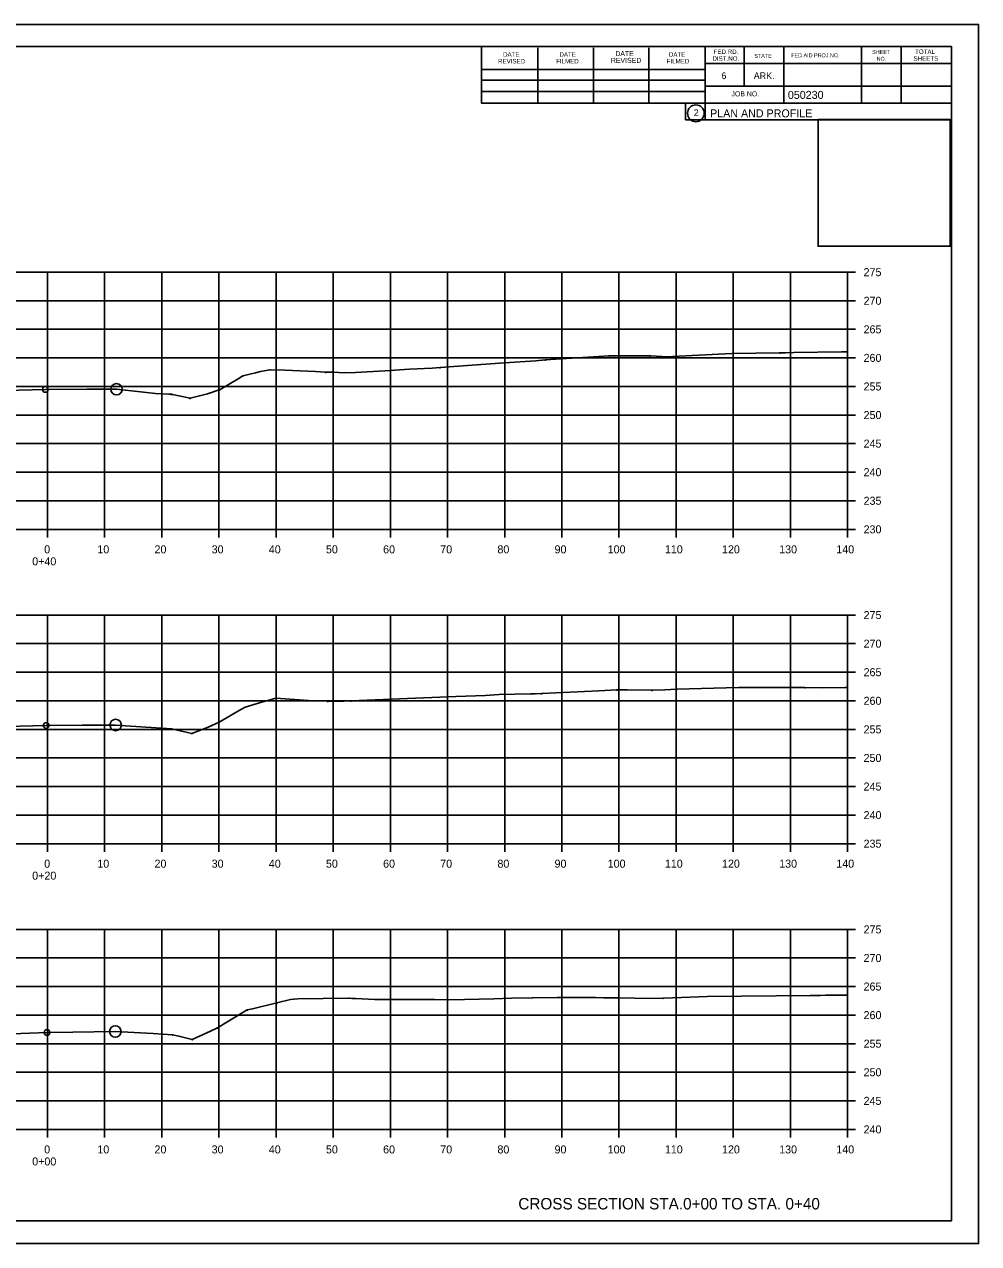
# Model space of a CAD drawing. Extents: x 1300404 to 1323571, y 234004 to 252077.
# Drawn here: x 1315713.2 to 1315880.2, y 239995.1 to 240208.4 of the extents above; entities that cross this region are included whole.
import ezdxf

# ---------------------------------------------------------------- set-up
doc = ezdxf.new("R2010")
doc.units = 0
for name, color, linetype in [('Default', 7, 'Continuous'), ('R_Axis', 7, 'Continuous'), ('R_Axis Annot', 7, 'Continuous'), ('R_Border', 7, 'Continuous'), ('R_Border Prem', 7, 'Continuous'), ('R_Draft', 7, 'Continuous'), ('R_Exist Surface', 7, 'Continuous'), ('R_Grid', 7, 'Continuous'), ('R_No Plot', 7, 'Continuous')]:
    doc.layers.add(name, color=color, linetype=linetype)

msp = doc.modelspace()

# ---------------------------------------------------------------- linework, layer by layer
at = {"layer": 'Default'}
for p, q in [((1315559.28, 240204.52), (1315875.46, 240204.52)), ((1315793.2, 240194.64), (1315793.2, 240204.52)), ((1315803.06, 240194.64), (1315803.06, 240204.32)), ((1315812.82, 240194.64), (1315812.82, 240204.32)), ((1315822.5, 240194.64), (1315822.5, 240204.32)), ((1315832.36, 240204.52), (1315832.36, 240191.72)), ((1315839.2, 240204.52), (1315839.2, 240197.58)), ((1315846.14, 240204.52), (1315846.14, 240194.64)), ((1315859.72, 240204.52), (1315859.72, 240194.64)), ((1315866.66, 240204.52), (1315866.66, 240194.64)), ((1315875.46, 239999.06), (1315875.46, 240204.52)), ((1315875.46, 240201.58), (1315832.36, 240201.58)), ((1315875.46, 240201.6), (1315875.46, 240201.6)), ((1315793.2, 240200.5), (1315832.36, 240200.5)), ((1315793.2, 240198.64), (1315832.36, 240198.64)), ((1315875.46, 240197.58), (1315832.36, 240197.58)), ((1315835.32, 240197.58), (1315875.46, 240197.58)), ((1315793.2, 240194.64), (1315793.2, 240196.7)), ((1315793.2, 240196.7), (1315832.36, 240196.7)), ((1315875.46, 240194.64), (1315793.2, 240194.64)), ((1315832.36, 240191.72), (1315875.46, 240191.72)), ((1315875.46, 239999.06), (1315559.28, 239999.06))]:
    msp.add_line(p, q, dxfattribs=at)
msp.add_circle((1315830.74, 240192.86), 1.47, dxfattribs=at)
at = {"layer": 'R_Axis'}
for p, q in [((1315857.28, 240120.06), (1315857.28, 240165.06)), ((1315858.68, 240165.06), (1315857.28, 240165.06)), ((1315858.68, 240160.06), (1315857.28, 240160.06)), ((1315858.68, 240155.06), (1315857.28, 240155.06)), ((1315858.68, 240150.06), (1315857.28, 240150.06)), ((1315858.68, 240145.06), (1315857.28, 240145.06)), ((1315858.68, 240140.06), (1315857.28, 240140.06)), ((1315858.68, 240135.06), (1315857.28, 240135.06)), ((1315858.68, 240130.06), (1315857.28, 240130.06)), ((1315858.68, 240125.06), (1315857.28, 240125.06)), ((1315577.28, 240120.06), (1315857.28, 240120.06)), ((1315717.28, 240118.66), (1315717.28, 240120.06)), ((1315727.28, 240118.66), (1315727.28, 240120.06)), ((1315737.28, 240118.66), (1315737.28, 240120.06)), ((1315747.28, 240118.66), (1315747.28, 240120.06)), ((1315757.28, 240118.66), (1315757.28, 240120.06)), ((1315767.28, 240118.66), (1315767.28, 240120.06)), ((1315777.28, 240118.66), (1315777.28, 240120.06)), ((1315787.28, 240118.66), (1315787.28, 240120.06)), ((1315797.28, 240118.66), (1315797.28, 240120.06)), ((1315807.28, 240118.66), (1315807.28, 240120.06)), ((1315817.28, 240118.66), (1315817.28, 240120.06)), ((1315827.28, 240118.66), (1315827.28, 240120.06)), ((1315837.28, 240118.66), (1315837.28, 240120.06)), ((1315847.28, 240118.66), (1315847.28, 240120.06)), ((1315857.28, 240118.66), (1315857.28, 240120.06)), ((1315858.68, 240120.06), (1315857.28, 240120.06)), ((1315857.28, 240065.06), (1315857.28, 240105.06)), ((1315858.68, 240105.06), (1315857.28, 240105.06)), ((1315858.68, 240100.06), (1315857.28, 240100.06)), ((1315858.68, 240095.06), (1315857.28, 240095.06)), ((1315858.68, 240090.06), (1315857.28, 240090.06)), ((1315858.68, 240085.06), (1315857.28, 240085.06)), ((1315858.68, 240080.06), (1315857.28, 240080.06)), ((1315858.68, 240075.06), (1315857.28, 240075.06)), ((1315858.68, 240070.06), (1315857.28, 240070.06)), ((1315577.28, 240065.06), (1315857.28, 240065.06)), ((1315717.28, 240063.66), (1315717.28, 240065.06)), ((1315727.28, 240063.66), (1315727.28, 240065.06)), ((1315737.28, 240063.66), (1315737.28, 240065.06)), ((1315747.28, 240063.66), (1315747.28, 240065.06)), ((1315757.28, 240063.66), (1315757.28, 240065.06)), ((1315767.28, 240063.66), (1315767.28, 240065.06)), ((1315777.28, 240063.66), (1315777.28, 240065.06)), ((1315787.28, 240063.66), (1315787.28, 240065.06)), ((1315797.28, 240063.66), (1315797.28, 240065.06)), ((1315807.28, 240063.66), (1315807.28, 240065.06)), ((1315817.28, 240063.66), (1315817.28, 240065.06)), ((1315827.28, 240063.66), (1315827.28, 240065.06)), ((1315837.28, 240063.66), (1315837.28, 240065.06)), ((1315847.28, 240063.66), (1315847.28, 240065.06)), ((1315857.28, 240063.66), (1315857.28, 240065.06)), ((1315858.68, 240065.06), (1315857.28, 240065.06)), ((1315857.28, 240015.06), (1315857.28, 240050.06)), ((1315858.68, 240050.06), (1315857.28, 240050.06)), ((1315858.68, 240045.06), (1315857.28, 240045.06)), ((1315858.68, 240040.06), (1315857.28, 240040.06)), ((1315858.68, 240035.06), (1315857.28, 240035.06)), ((1315858.68, 240030.06), (1315857.28, 240030.06)), ((1315858.68, 240025.06), (1315857.28, 240025.06)), ((1315858.68, 240020.06), (1315857.28, 240020.06)), ((1315577.28, 240015.06), (1315857.28, 240015.06)), ((1315717.28, 240013.66), (1315717.28, 240015.06)), ((1315727.28, 240013.66), (1315727.28, 240015.06)), ((1315737.28, 240013.66), (1315737.28, 240015.06)), ((1315747.28, 240013.66), (1315747.28, 240015.06)), ((1315757.28, 240013.66), (1315757.28, 240015.06)), ((1315767.28, 240013.66), (1315767.28, 240015.06)), ((1315777.28, 240013.66), (1315777.28, 240015.06)), ((1315787.28, 240013.66), (1315787.28, 240015.06)), ((1315797.28, 240013.66), (1315797.28, 240015.06)), ((1315807.28, 240013.66), (1315807.28, 240015.06)), ((1315817.28, 240013.66), (1315817.28, 240015.06)), ((1315827.28, 240013.66), (1315827.28, 240015.06)), ((1315837.28, 240013.66), (1315837.28, 240015.06)), ((1315847.28, 240013.66), (1315847.28, 240015.06)), ((1315857.28, 240013.66), (1315857.28, 240015.06)), ((1315858.68, 240015.06), (1315857.28, 240015.06))]:
    msp.add_line(p, q, dxfattribs=at)
at = {"layer": 'R_Draft'}
for points in [[(1315815.58, 240150.48), (1315815.63, 240150.38), (1315815.53, 240150.38)], [(1315822.72, 240150.47), (1315822.77, 240150.37), (1315822.67, 240150.37)], [(1315845.44, 240151.01), (1315845.49, 240150.91), (1315845.39, 240150.91)], [(1315756.17, 240148.05), (1315756.22, 240147.95), (1315756.12, 240147.95)], [(1315785.98, 240148.41), (1315786.03, 240148.31), (1315785.93, 240148.31)], [(1315804.38, 240149.75), (1315804.43, 240149.65), (1315804.33, 240149.65)], [(1315751.49, 240146.97), (1315751.54, 240146.87), (1315751.44, 240146.87)], [(1315765.91, 240147.61), (1315765.96, 240147.51), (1315765.86, 240147.51)], [(1315738.97, 240143.74), (1315739.02, 240143.64), (1315738.92, 240143.64)], [(1315747.5, 240144.59), (1315747.55, 240144.49), (1315747.45, 240144.49)], [(1315742.24, 240143.05), (1315742.29, 240142.95), (1315742.19, 240142.95)], [(1315849.8, 240092.41), (1315849.85, 240092.31), (1315849.75, 240092.31)], [(1315757.26, 240090.58), (1315757.31, 240090.48), (1315757.21, 240090.48)], [(1315803.75, 240091.36), (1315803.8, 240091.26), (1315803.7, 240091.26)], [(1315816.9, 240092.03), (1315816.95, 240091.93), (1315816.85, 240091.93)], [(1315823.06, 240091.95), (1315823.11, 240091.85), (1315823.01, 240091.85)], [(1315827.4, 240092.15), (1315827.45, 240092.05), (1315827.35, 240092.05)], [(1315751.88, 240089.02), (1315751.93, 240088.92), (1315751.83, 240088.92)], [(1315766.29, 240090.03), (1315766.34, 240089.93), (1315766.24, 240089.93)], [(1315770.41, 240090.08), (1315770.46, 240089.98), (1315770.36, 240089.98)], [(1315747.32, 240086.35), (1315747.37, 240086.25), (1315747.27, 240086.25)], [(1315739.06, 240085.18), (1315739.11, 240085.08), (1315739.01, 240085.08)], [(1315742.54, 240084.4), (1315742.59, 240084.3), (1315742.49, 240084.3)], [(1315757.44, 240037.26), (1315757.49, 240037.16), (1315757.39, 240037.16)], [(1315802.15, 240038.16), (1315802.2, 240038.06), (1315802.1, 240038.06)], [(1315824.98, 240038.09), (1315825.03, 240037.99), (1315824.93, 240037.99)], [(1315850.79, 240038.57), (1315850.84, 240038.47), (1315850.74, 240038.47)], [(1315752.25, 240036.01), (1315752.3, 240035.91), (1315752.2, 240035.91)], [(1315747.04, 240032.88), (1315747.09, 240032.78), (1315746.99, 240032.78)], [(1315739.15, 240031.68), (1315739.2, 240031.58), (1315739.1, 240031.58)], [(1315742.61, 240030.84), (1315742.66, 240030.74), (1315742.56, 240030.74)]]:
    msp.add_lwpolyline(points, close=True, dxfattribs=at)
at = {"layer": 'R_Exist Surface'}
for points in [[(1315709.91, 240144.38), (1315716.91, 240144.54), (1315724.17, 240144.57), (1315729.36, 240144.57), (1315736.19, 240143.84), (1315738.51, 240143.72), (1315738.97, 240143.69), (1315739.13, 240143.65), (1315742.24, 240143), (1315745.26, 240143.78), (1315747.5, 240144.54), (1315750.64, 240146.42), (1315751.49, 240146.92), (1315753.68, 240147.45), (1315754.56, 240147.7), (1315756.17, 240148), (1315758.82, 240147.91), (1315764.18, 240147.68), (1315765.91, 240147.56), (1315767.21, 240147.56), (1315769.3, 240147.47), (1315771.2, 240147.49), (1315776.29, 240147.79), (1315780.61, 240148.06), (1315784.59, 240148.25), (1315785.98, 240148.36), (1315797.21, 240149.18), (1315802.73, 240149.56), (1315804.38, 240149.7), (1315805.31, 240149.78), (1315815.58, 240150.43), (1315816.86, 240150.44), (1315822.72, 240150.42), (1315825.88, 240150.24), (1315826.25, 240150.26), (1315826.62, 240150.28), (1315837.04, 240150.85), (1315845.44, 240150.96), (1315846.4, 240150.96), (1315847.85, 240150.98), (1315856.23, 240151.11), (1315857.28, 240151.11)], [(1315707.7, 240085.49), (1315717.07, 240085.72), (1315723.38, 240085.79), (1315729.21, 240085.82), (1315737.16, 240085.25), (1315739.06, 240085.13), (1315739.77, 240084.97), (1315742.54, 240084.35), (1315745.38, 240085.42), (1315747.32, 240086.3), (1315751.12, 240088.51), (1315751.88, 240088.97), (1315754.36, 240089.7), (1315757.26, 240090.53), (1315762.96, 240090.13), (1315766.29, 240089.98), (1315768.15, 240089.94), (1315769.16, 240089.97), (1315770.41, 240090.03), (1315788.72, 240090.84), (1315793.94, 240091), (1315796.32, 240091.15), (1315801.78, 240091.25), (1315802.64, 240091.28), (1315803.75, 240091.31), (1315813.73, 240091.79), (1315816.9, 240091.98), (1315818.74, 240091.96), (1315823.06, 240091.9), (1315825.3, 240091.99), (1315827.4, 240092.1), (1315838.17, 240092.37), (1315849.8, 240092.36), (1315852.9, 240092.33), (1315856.86, 240092.36), (1315857.28, 240092.37)], [(1315706.45, 240031.62), (1315717.2, 240032.04), (1315721.73, 240032.08), (1315729.15, 240032.19), (1315735.78, 240031.86), (1315739.15, 240031.63), (1315740.27, 240031.4), (1315742.61, 240030.79), (1315745.8, 240032.27), (1315747.04, 240032.83), (1315751.36, 240035.44), (1315752.25, 240035.96), (1315753.15, 240036.19), (1315757.44, 240037.21), (1315759.83, 240037.81), (1315761.1, 240037.93), (1315769.93, 240038.04), (1315770.15, 240038.03), (1315770.56, 240037.99), (1315770.73, 240037.97), (1315770.87, 240037.96), (1315771.06, 240037.95), (1315771.26, 240037.94), (1315774.55, 240037.8), (1315775.79, 240037.78), (1315785.02, 240037.78), (1315787.69, 240037.73), (1315795.4, 240037.91), (1315798.45, 240038), (1315802.15, 240038.11), (1315806.46, 240038.12), (1315811.16, 240038.14), (1315813.24, 240038.16), (1315814.55, 240038.1), (1315817.3, 240038.06), (1315822.79, 240037.97), (1315824.98, 240038.04), (1315825.06, 240038.04), (1315828.22, 240038.14), (1315832.7, 240038.32), (1315850.79, 240038.52), (1315852.52, 240038.52), (1315853.5, 240038.53), (1315857.28, 240038.53)]]:
    msp.add_lwpolyline(points, dxfattribs=at)
at = {"layer": 'R_Grid'}
for p, q in [((1315577.28, 240165.06), (1315857.28, 240165.06)), ((1315717.28, 240120.06), (1315717.28, 240165.06)), ((1315727.28, 240120.06), (1315727.28, 240165.06)), ((1315737.28, 240120.06), (1315737.28, 240165.06)), ((1315747.28, 240120.06), (1315747.28, 240165.06)), ((1315757.28, 240120.06), (1315757.28, 240165.06)), ((1315767.28, 240120.06), (1315767.28, 240165.06)), ((1315777.28, 240120.06), (1315777.28, 240165.06)), ((1315787.28, 240120.06), (1315787.28, 240165.06)), ((1315797.28, 240120.06), (1315797.28, 240165.06)), ((1315807.28, 240120.06), (1315807.28, 240165.06)), ((1315817.28, 240120.06), (1315817.28, 240165.06)), ((1315827.28, 240120.06), (1315827.28, 240165.06)), ((1315837.28, 240120.06), (1315837.28, 240165.06)), ((1315847.28, 240120.06), (1315847.28, 240165.06)), ((1315857.28, 240120.06), (1315857.28, 240165.06)), ((1315577.28, 240160.06), (1315857.28, 240160.06)), ((1315577.28, 240155.06), (1315857.28, 240155.06)), ((1315577.28, 240150.06), (1315857.28, 240150.06)), ((1315577.28, 240145.06), (1315857.28, 240145.06)), ((1315577.28, 240140.06), (1315857.28, 240140.06)), ((1315577.28, 240135.06), (1315857.28, 240135.06)), ((1315577.28, 240130.06), (1315857.28, 240130.06)), ((1315577.28, 240125.06), (1315857.28, 240125.06)), ((1315577.28, 240120.06), (1315857.28, 240120.06)), ((1315577.28, 240105.06), (1315857.28, 240105.06)), ((1315717.28, 240065.06), (1315717.28, 240105.06)), ((1315727.28, 240065.06), (1315727.28, 240105.06)), ((1315737.28, 240065.06), (1315737.28, 240105.06)), ((1315747.28, 240065.06), (1315747.28, 240105.06)), ((1315757.28, 240065.06), (1315757.28, 240105.06)), ((1315767.28, 240065.06), (1315767.28, 240105.06)), ((1315777.28, 240065.06), (1315777.28, 240105.06)), ((1315787.28, 240065.06), (1315787.28, 240105.06)), ((1315797.28, 240065.06), (1315797.28, 240105.06)), ((1315807.28, 240065.06), (1315807.28, 240105.06)), ((1315817.28, 240065.06), (1315817.28, 240105.06)), ((1315827.28, 240065.06), (1315827.28, 240105.06)), ((1315837.28, 240065.06), (1315837.28, 240105.06)), ((1315847.28, 240065.06), (1315847.28, 240105.06)), ((1315857.28, 240065.06), (1315857.28, 240105.06)), ((1315577.28, 240100.06), (1315857.28, 240100.06)), ((1315577.28, 240095.06), (1315857.28, 240095.06)), ((1315577.28, 240090.06), (1315857.28, 240090.06)), ((1315577.28, 240085.06), (1315857.28, 240085.06)), ((1315577.28, 240080.06), (1315857.28, 240080.06)), ((1315577.28, 240075.06), (1315857.28, 240075.06)), ((1315577.28, 240070.06), (1315857.28, 240070.06)), ((1315577.28, 240065.06), (1315857.28, 240065.06)), ((1315577.28, 240050.06), (1315857.28, 240050.06)), ((1315717.28, 240015.06), (1315717.28, 240050.06)), ((1315727.28, 240015.06), (1315727.28, 240050.06)), ((1315737.28, 240015.06), (1315737.28, 240050.06)), ((1315747.28, 240015.06), (1315747.28, 240050.06)), ((1315757.28, 240015.06), (1315757.28, 240050.06)), ((1315767.28, 240015.06), (1315767.28, 240050.06)), ((1315777.28, 240015.06), (1315777.28, 240050.06)), ((1315787.28, 240015.06), (1315787.28, 240050.06)), ((1315797.28, 240015.06), (1315797.28, 240050.06)), ((1315807.28, 240015.06), (1315807.28, 240050.06)), ((1315817.28, 240015.06), (1315817.28, 240050.06)), ((1315827.28, 240015.06), (1315827.28, 240050.06)), ((1315837.28, 240015.06), (1315837.28, 240050.06)), ((1315847.28, 240015.06), (1315847.28, 240050.06)), ((1315857.28, 240015.06), (1315857.28, 240050.06)), ((1315577.28, 240045.06), (1315857.28, 240045.06)), ((1315577.28, 240040.06), (1315857.28, 240040.06)), ((1315577.28, 240035.06), (1315857.28, 240035.06)), ((1315577.28, 240030.06), (1315857.28, 240030.06)), ((1315577.28, 240025.06), (1315857.28, 240025.06)), ((1315577.28, 240020.06), (1315857.28, 240020.06)), ((1315577.28, 240015.06), (1315857.28, 240015.06))]:
    msp.add_line(p, q, dxfattribs=at)
at = {"layer": 'R_No Plot'}
for p, q in [((1315546.87, 240208.42), (1315880.21, 240208.42)), ((1315546.87, 239995.08), (1315880.21, 239995.08))]:
    msp.add_line(p, q, dxfattribs=at)
for points in [[(1315546.87, 240208.42), (1315880.21, 240208.42), (1315880.21, 239995.08), (1315546.87, 239995.08)], [(1315793.2, 240204.52), (1315793.2, 240194.64), (1315828.93, 240194.64), (1315828.93, 240191.72), (1315852.13, 240191.72), (1315852.13, 240169.6), (1315875.46, 240169.6), (1315875.46, 239999.06), (1315559.28, 239999.06), (1315559.28, 240204.52)], [(1315852.13, 240191.75), (1315875.23, 240191.75), (1315875.23, 240169.6), (1315852.13, 240169.6)]]:
    msp.add_lwpolyline(points, close=True, dxfattribs=at)
for centre, radius in [((1315716.91, 240144.54), 0.5), ((1315729.36, 240144.57), 1), ((1315717.07, 240085.72), 0.5), ((1315729.21, 240085.82), 1), ((1315717.2, 240032.04), 0.5), ((1315729.15, 240032.19), 1)]:
    msp.add_circle(centre, radius, dxfattribs=at)

# ---------------------------------------------------------------- texts
at = {"layer": 'Default'}
msp.add_text('2', height=1.17, dxfattribs=at).set_placement((1315830.36, 240192.37))
at = {"layer": 'R_Axis Annot'}
for s, p in [('275', (1315860.08, 240164.36)), ('270', (1315860.08, 240159.36)), ('265', (1315860.08, 240154.36)), ('260', (1315860.08, 240149.36)), ('255', (1315860.08, 240144.36)), ('250', (1315860.08, 240139.36)), ('245', (1315860.08, 240134.36)), ('240', (1315860.08, 240129.36)), ('235', (1315860.08, 240124.36)), ('230', (1315860.08, 240119.36)), ('0', (1315716.71, 240115.86)), ('10', (1315726.01, 240115.86)), ('20', (1315736.01, 240115.86)), ('30', (1315746.01, 240115.86)), ('40', (1315756.01, 240115.86)), ('50', (1315766.01, 240115.86)), ('60', (1315776.01, 240115.86)), ('70', (1315786.01, 240115.86)), ('80', (1315796.01, 240115.86)), ('90', (1315806.01, 240115.86)), ('100', (1315815.31, 240115.86)), ('110', (1315825.31, 240115.86)), ('120', (1315835.31, 240115.86)), ('130', (1315845.31, 240115.86)), ('140', (1315855.31, 240115.86)), ('0+40', (1315714.61, 240113.76)), ('275', (1315860.08, 240104.36)), ('270', (1315860.08, 240099.36)), ('265', (1315860.08, 240094.36)), ('260', (1315860.08, 240089.36)), ('255', (1315860.08, 240084.36)), ('250', (1315860.08, 240079.36)), ('245', (1315860.08, 240074.36)), ('240', (1315860.08, 240069.36)), ('235', (1315860.08, 240064.36)), ('0', (1315716.71, 240060.86)), ('10', (1315726.01, 240060.86)), ('20', (1315736.01, 240060.86)), ('30', (1315746.01, 240060.86)), ('40', (1315756.01, 240060.86)), ('50', (1315766.01, 240060.86)), ('60', (1315776.01, 240060.86)), ('70', (1315786.01, 240060.86)), ('80', (1315796.01, 240060.86)), ('90', (1315806.01, 240060.86)), ('100', (1315815.31, 240060.86)), ('110', (1315825.31, 240060.86)), ('120', (1315835.31, 240060.86)), ('130', (1315845.31, 240060.86)), ('140', (1315855.31, 240060.86)), ('0+20', (1315714.61, 240058.76)), ('275', (1315860.08, 240049.36)), ('270', (1315860.08, 240044.36)), ('265', (1315860.08, 240039.36)), ('260', (1315860.08, 240034.36)), ('255', (1315860.08, 240029.36)), ('250', (1315860.08, 240024.36)), ('245', (1315860.08, 240019.36)), ('240', (1315860.08, 240014.36)), ('0', (1315716.71, 240010.86)), ('10', (1315726.01, 240010.86)), ('20', (1315736.01, 240010.86)), ('30', (1315746.01, 240010.86)), ('40', (1315756.01, 240010.86)), ('50', (1315766.01, 240010.86)), ('60', (1315776.01, 240010.86)), ('70', (1315786.01, 240010.86)), ('80', (1315796.01, 240010.86)), ('90', (1315806.01, 240010.86)), ('100', (1315815.31, 240010.86)), ('110', (1315825.31, 240010.86)), ('120', (1315835.31, 240010.86)), ('130', (1315845.31, 240010.86)), ('140', (1315855.31, 240010.86)), ('0+00', (1315714.61, 240008.76))]:
    msp.add_text(s, height=1.4, dxfattribs=at).set_placement(p)
at = {"layer": 'R_Border'}
for s, height, p in [('DATE', 0.782, (1315797, 240202.76)), ('DATE', 0.782, (1315806.86, 240202.76)), ('DATE', 0.879, (1315816.64, 240202.86)), ('DATE', 0.782, (1315826.02, 240202.76)), ('FED.RD.', 0.782, (1315833.84, 240203.24)), ('STATE', 0.684, (1315840.96, 240202.56)), ('FED.AID PROJ.NO.', 0.684, (1315847.42, 240202.66)), ('SHEET', 0.684, (1315861.58, 240203.24)), ('TOTAL', 0.782, (1315869.1, 240203.24)), ('REVISED', 0.782, (1315796.12, 240201.58)), ('FILMED', 0.782, (1315806.28, 240201.58)), ('REVISED', 0.879, (1315815.86, 240201.68)), ('FILMED', 0.782, (1315825.62, 240201.58)), ('DIST.NO.', 0.782, (1315833.64, 240202.06)), ('NO.', 0.684, (1315862.36, 240202.06)), ('SHEETS', 0.782, (1315868.82, 240202.06)), ('6', 1.17, (1315835.2, 240198.84)), ('ARK.', 1.172, (1315840.86, 240198.84)), ('JOB NO.', 0.879, (1315836.96, 240195.82))]:
    msp.add_text(s, height=height, dxfattribs=at).set_placement(p)
for s, p in [('050230', (1315846.83, 240195.38)), ('PLAN AND PROFILE', (1315833.22, 240192.15))]:
    msp.add_text(s, height=1.4, rotation=360, dxfattribs=at).set_placement(p)
at = {"layer": 'R_Border Prem'}
msp.add_text('DWB', height=0.01, dxfattribs=at).set_placement((1315836.15, 240186.03))
at = {"layer": 'R_Draft'}
msp.add_text('CROSS SECTION STA.0+00 TO STA. 0+40', height=2, dxfattribs=at).set_placement((1315799.67, 240001.06))

doc.saveas('drawing.dxf')
